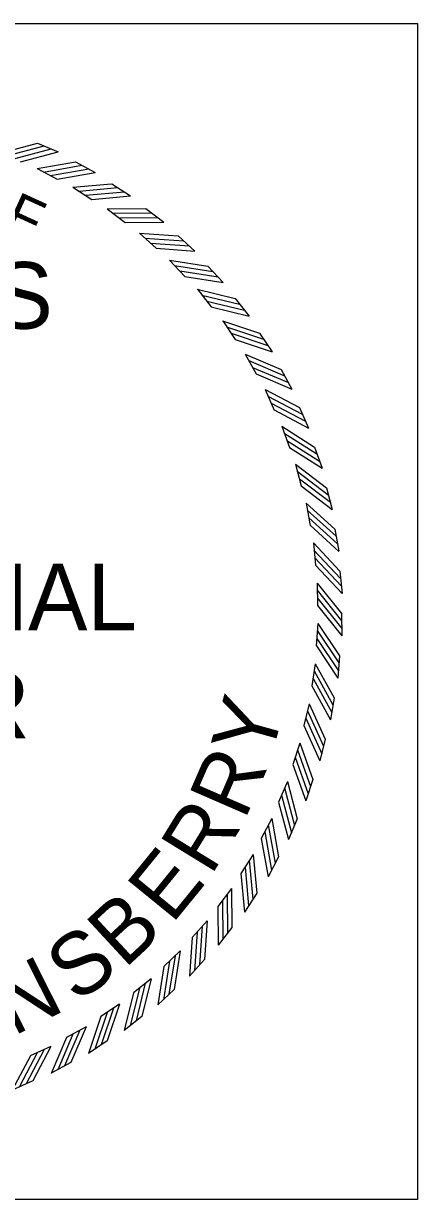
# Model space of a CAD drawing. Extents: x 0 to 1228740, y 0 to 152440.
# Drawn here: x 36.607 to 37.53, y 17.436 to 20.192 of the extents above; entities that cross this region are included whole.
import ezdxf

# ---------------------------------------------------------------- set-up
doc = ezdxf.new("R2010")
doc.units = 0
doc.layers.add('R_Sheet Text', color=7, linetype='Continuous')

msp = doc.modelspace()

# ---------------------------------------------------------------- linework, layer by layer
at = {"layer": 'R_Sheet Text'}
for p, q in [((36.6395, 19.9118), (36.6879, 19.8911)), ((36.6387, 19.8519), (36.6854, 19.8272)), ((36.7284, 19.8678), (36.7749, 19.8432)), ((36.7227, 19.8081), (36.7671, 19.7797)), ((36.8134, 19.8166), (36.8577, 19.7882)), ((36.8027, 19.7576), (36.8447, 19.7256)), ((36.8938, 19.7585), (36.9356, 19.7266)), ((36.8783, 19.7006), (36.9175, 19.6653)), ((36.9692, 19.694), (37.0082, 19.6587)), ((36.949, 19.6376), (36.9851, 19.5991)), ((37.0389, 19.6235), (37.0749, 19.5851)), ((37.0142, 19.569), (37.0469, 19.5276)), ((37.1027, 19.5475), (37.1354, 19.5063)), ((37.0735, 19.4952), (37.1027, 19.4513)), ((37.1599, 19.4665), (37.1891, 19.4227)), ((37.1265, 19.4168), (37.152, 19.3706)), ((37.2102, 19.381), (37.2357, 19.335)), ((37.1728, 19.3342), (37.1945, 19.2861)), ((37.2533, 19.2917), (37.2749, 19.2437)), ((37.2122, 19.2481), (37.2298, 19.1984)), ((37.2889, 19.1991), (37.3065, 19.1495)), ((37.2443, 19.1591), (37.2577, 19.1081)), ((37.3168, 19.1039), (37.3301, 19.053)), ((37.269, 19.0677), (37.2782, 19.0157)), ((37.3366, 19.0067), (37.3457, 18.9549)), ((37.286, 18.9746), (37.2909, 18.922)), ((37.3484, 18.9082), (37.3532, 18.8558)), ((37.2953, 18.8804), (37.2958, 18.8276)), ((37.352, 18.8091), (37.3525, 18.7564)), ((37.2968, 18.7857), (37.2929, 18.7331)), ((37.2904, 18.6913), (37.2822, 18.6392)), ((37.3474, 18.71), (37.3435, 18.6575)), ((37.3346, 18.6116), (37.3264, 18.5596)), ((37.2763, 18.5976), (37.2638, 18.5464)), ((37.2545, 18.5055), (37.2379, 18.4555)), ((37.3137, 18.5146), (37.3013, 18.4635)), ((37.2252, 18.4155), (37.2044, 18.367)), ((37.285, 18.4197), (37.2683, 18.3698)), ((37.1885, 18.3283), (37.1638, 18.2816)), ((37.2484, 18.3275), (37.2277, 18.2791)), ((37.1448, 18.2443), (37.1163, 18.1999)), ((37.2044, 18.2386), (37.1798, 18.1921)), ((37.0942, 18.1643), (37.0622, 18.1223)), ((37.1532, 18.1536), (37.1248, 18.1093)), ((37.0373, 18.0887), (37.0019, 18.0495)), ((37.0951, 18.0732), (37.0632, 18.0314)), ((36.9742, 18.018), (36.9358, 17.9819)), ((37.0307, 17.9978), (36.9954, 17.9588)), ((36.9056, 17.9528), (36.8643, 17.9201)), ((36.9602, 17.9281), (36.9218, 17.8921)), ((36.8318, 17.8935), (36.7879, 17.8643)), ((36.8841, 17.8643), (36.8429, 17.8316)), ((36.7534, 17.8405), (36.7072, 17.815)), ((36.8031, 17.8071), (36.7593, 17.7779)), ((36.6708, 17.7942), (36.6227, 17.7725)), ((36.7176, 17.7568), (36.6716, 17.7313)), ((36.6283, 17.7137), (36.5803, 17.6921))]:
    msp.add_line(p, q, dxfattribs=at)
msp.add_lwpolyline([(34.7735, 20.192), (37.53, 20.192), (37.53, 17.4355), (34.7735, 17.4355)], close=True, dxfattribs=at)
for points in [[(36.5514, 19.8885), (36.6394, 19.9118)], [(36.5669, 19.8817), (36.6549, 19.905)], [(36.5839, 19.8749), (36.6719, 19.8982)], [(36.5999, 19.8679), (36.688, 19.8911)], [(36.6387, 19.8519), (36.7283, 19.8678)], [(36.6536, 19.8438), (36.7432, 19.8597)], [(36.6699, 19.8356), (36.7596, 19.8515)], [(36.6853, 19.8273), (36.775, 19.8432)], [(36.7226, 19.8081), (36.8133, 19.8166)], [(36.7368, 19.7989), (36.8275, 19.8073)], [(36.7524, 19.7893), (36.8431, 19.7978)], [(36.7671, 19.7798), (36.8577, 19.7882)], [(36.8027, 19.7576), (36.8937, 19.7585)], [(36.816, 19.7472), (36.9071, 19.7481)], [(36.8308, 19.7364), (36.9218, 19.7374)], [(36.8446, 19.7257), (36.9357, 19.7266)], [(36.8783, 19.7006), (36.9691, 19.694)], [(36.8907, 19.6892), (36.9815, 19.6826)], [(36.9046, 19.6772), (36.9954, 19.6706)], [(36.9175, 19.6653), (37.0083, 19.6587)], [(36.9489, 19.6376), (37.0389, 19.6236)], [(36.9604, 19.6252), (37.0503, 19.6111)], [(36.9732, 19.6121), (37.0631, 19.598)], [(36.985, 19.5992), (37.075, 19.5851)], [(37.0141, 19.569), (37.1026, 19.5475)], [(37.0245, 19.5556), (37.113, 19.5342)], [(37.0362, 19.5416), (37.1247, 19.5201)], [(37.0469, 19.5277), (37.1354, 19.5063)], [(37.0734, 19.4952), (37.1598, 19.4665)], [(37.0827, 19.481), (37.1691, 19.4523)], [(37.0931, 19.466), (37.1796, 19.4374)], [(37.1027, 19.4514), (37.1891, 19.4227)], [(37.1264, 19.4168), (37.2102, 19.3811)], [(37.1345, 19.4019), (37.2182, 19.3662)], [(37.1437, 19.3861), (37.2274, 19.3504)], [(37.152, 19.3707), (37.2358, 19.3349)], [(37.1728, 19.3342), (37.2533, 19.2917)], [(37.1796, 19.3187), (37.2601, 19.2762)], [(37.1874, 19.3022), (37.2679, 19.2597)], [(37.1945, 19.2862), (37.275, 19.2437)], [(37.2121, 19.2482), (37.2889, 19.1991)], [(37.2176, 19.2321), (37.2944, 19.1831)], [(37.2241, 19.215), (37.3008, 19.166)], [(37.2298, 19.1985), (37.3065, 19.1494)], [(37.2443, 19.1591), (37.3167, 19.1039)], [(37.2484, 19.1427), (37.3208, 19.0875)], [(37.2535, 19.1251), (37.3259, 19.0699)], [(37.2578, 19.1081), (37.3302, 19.0529)], [(37.2689, 19.0677), (37.3365, 19.0068)], [(37.2717, 19.051), (37.3393, 18.99)], [(37.2753, 19.0331), (37.3429, 18.9721)], [(37.2782, 19.0158), (37.3458, 18.9548)], [(37.286, 18.9746), (37.3483, 18.9083)], [(37.2874, 18.9577), (37.3497, 18.8914)], [(37.2895, 18.9396), (37.3518, 18.8732)], [(37.2909, 18.9221), (37.3532, 18.8558)], [(37.2953, 18.8804), (37.3519, 18.8091)], [(37.2953, 18.8635), (37.3519, 18.7922)], [(37.2958, 18.8452), (37.3525, 18.7739)], [(37.2958, 18.8277), (37.3525, 18.7564)], [(37.2967, 18.7858), (37.3473, 18.7101)], [(37.2944, 18.7506), (37.345, 18.6749)], [(37.2953, 18.7689), (37.3459, 18.6932)], [(37.293, 18.7332), (37.3435, 18.6574)], [(37.2904, 18.6913), (37.3346, 18.6117)], [(37.2876, 18.6746), (37.3318, 18.595)], [(37.2823, 18.6392), (37.3264, 18.5596)], [(37.2852, 18.6565), (37.3293, 18.5769)], [(37.2721, 18.5813), (37.3096, 18.4983)], [(37.2763, 18.5977), (37.3137, 18.5147)], [(37.2682, 18.5634), (37.3056, 18.4804)], [(37.2639, 18.5465), (37.3013, 18.4634)], [(37.2545, 18.5056), (37.2849, 18.4198)], [(37.2436, 18.4721), (37.274, 18.3863)], [(37.249, 18.4896), (37.2794, 18.4038)], [(37.2379, 18.4555), (37.2683, 18.3697)], [(37.2252, 18.4156), (37.2484, 18.3276)], [(37.2184, 18.4001), (37.2416, 18.3121)], [(37.2045, 18.3671), (37.2277, 18.279)], [(37.2115, 18.3831), (37.2348, 18.2951)], [(37.1804, 18.3134), (37.1963, 18.2238)], [(37.1885, 18.3283), (37.2044, 18.2387)], [(37.1639, 18.2817), (37.1798, 18.192)], [(37.1722, 18.2971), (37.1881, 18.2074)], [(37.1355, 18.2302), (37.1439, 18.1395)], [(37.1448, 18.2444), (37.1532, 18.1537)], [(37.1164, 18.1999), (37.1248, 18.1093)], [(37.126, 18.2146), (37.1344, 18.1239)], [(37.0838, 18.151), (37.0847, 18.0599)], [(37.0942, 18.1643), (37.0952, 18.0733)], [(37.0623, 18.1224), (37.0632, 18.0313)], [(37.073, 18.1362), (37.074, 18.0452)], [(37.0373, 18.0887), (37.0307, 17.9979)], [(37.0138, 18.0624), (37.0072, 17.9716)], [(37.0258, 18.0763), (37.0192, 17.9855)], [(37.002, 18.0495), (36.9954, 17.9587)], [(36.9618, 18.0066), (36.9477, 17.9167)], [(36.9742, 18.0181), (36.9602, 17.9281)], [(36.9358, 17.982), (36.9218, 17.892)], [(36.9487, 17.9938), (36.9347, 17.9039)], [(36.9056, 17.9529), (36.8842, 17.8644)], [(36.8643, 17.9201), (36.8429, 17.8316)], [(36.8782, 17.9308), (36.8567, 17.8423)], [(36.8922, 17.9425), (36.8708, 17.854)], [(36.8318, 17.8936), (36.8031, 17.8072)], [(36.788, 17.8643), (36.7593, 17.7779)], [(36.8027, 17.8739), (36.774, 17.7875)], [(36.8177, 17.8843), (36.789, 17.7979)], [(36.7534, 17.8406), (36.7177, 17.7568)], [(36.7073, 17.815), (36.6716, 17.7312)], [(36.7227, 17.8233), (36.687, 17.7396)], [(36.7385, 17.8325), (36.7028, 17.7488)], [(36.6389, 17.7796), (36.5963, 17.6991)], [(36.6554, 17.7874), (36.6128, 17.7069)], [(36.6709, 17.7942), (36.6284, 17.7137)], [(36.6228, 17.7725), (36.5803, 17.692)]]:
    msp.add_lwpolyline(points, dxfattribs=at)

# ---------------------------------------------------------------- texts
for s, height, rotation, p in [('F', 0.0957, 335.3628, (36.5552, 19.7122)), ('Y', 0.1454, 74.5264, (37.1848, 18.4627)), ('R', 0.1454, 66.5008, (37.1249, 18.3225)), ('R', 0.1454, 58.4752, (37.046, 18.192)), ('E', 0.1454, 50.8144, (36.9544, 18.0788)), ('B', 0.1454, 42.7888, (36.8431, 17.9745)), ('S', 0.1454, 35.4928, (36.7302, 17.894)), ('N', 0.1454, 26.7376, (36.5826, 17.8173))]:
    msp.add_text(s, height=height, rotation=rotation, dxfattribs=at).set_placement(p)
for s, height, p in [('ARKANSAS', 0.15625, (35.5376, 19.4766)), ('PROFESSIONAL', 0.156246, (35.2474, 18.7695)), ('ENGINEER', 0.15625, (35.5302, 18.5165))]:
    msp.add_text(s, height=height, dxfattribs=at).set_placement(p)

doc.saveas('drawing.dxf')
